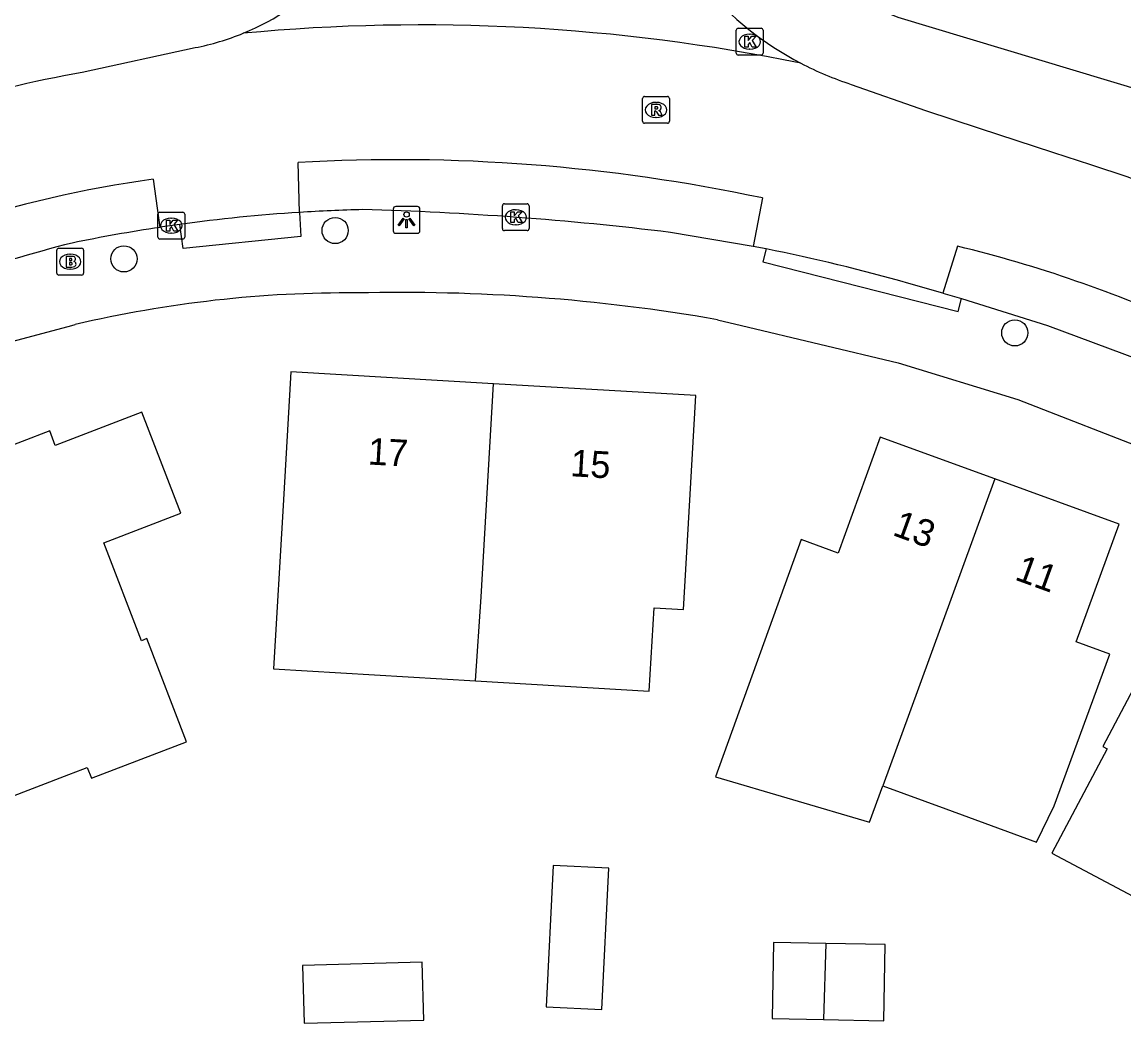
# Model space of a CAD drawing. Extents: x 161354 to 161876, y 382161 to 382804.
# Drawn here: x 161643.37 to 161684.52, y 382473.49 to 382511.32 of the extents above; entities that cross this region are included whole.
import ezdxf

# ---------------------------------------------------------------- set-up
doc = ezdxf.new("R2010")
doc.units = 0
for name, color, linetype in [('IMGEO_Boom', 7, 'Continuous'), ('IMGEO_Brandkraan', 7, 'Continuous'), ('IMGEO_Kolk', 7, 'Continuous'), ('IMGEO_Lichtpunt', 7, 'Continuous'), ('IMGEO_Pand', 7, 'Continuous'), ('IMGEO_Pand_nummerreeks', 7, 'Continuous'), ('IMGEO_Rijbaan_lokaal_gesloten', 7, 'Continuous'), ('IMGEO_Rijbaan_lokaal_open', 7, 'Continuous'), ('IMGEO_Rioolput', 7, 'Continuous'), ('IMGEO_Voetpad_open', 7, 'Continuous')]:
    doc.layers.add(name, color=color, linetype=linetype)

msp = doc.modelspace()

# ---------------------------------------------------------------- linework, layer by layer
at = {"layer": 'IMGEO_Boom'}
for centre in [(161655.065, 382503.541), (161647.18, 382502.485), (161680.442, 382499.723)]:
    msp.add_circle(centre, 0.489, dxfattribs=at)
at = {"layer": 'IMGEO_Brandkraan'}
for p, q in [((161644.672, 382501.953), (161644.672, 382502.805)), ((161644.747, 382502.879), (161645.599, 382502.879)), ((161645.16, 382502.659), (161645.185, 382502.659)), ((161645.673, 382502.805), (161645.673, 382501.953)), ((161645.183, 382502.099), (161645.158, 382502.099)), ((161645.599, 382501.879), (161644.747, 382501.879))]:
    msp.add_line(p, q, dxfattribs=at)
for points in [[(161644.672, 382501.953), (161644.672, 382502.805)], [(161644.747, 382502.879), (161645.599, 382502.879)], [(161645.02, 382502.579), (161645.02, 382502.179), (161645.233, 382502.179)], [(161645.251, 382502.579), (161645.02, 382502.579)], [(161645.199, 382502.498), (161645.145, 382502.498), (161645.145, 382502.422)], [(161645.673, 382502.805), (161645.673, 382501.953)], [(161645.145, 382502.422), (161645.198, 382502.422)], [(161645.207, 382502.346), (161645.145, 382502.346), (161645.145, 382502.265)], [(161645.145, 382502.265), (161645.207, 382502.265)], [(161645.599, 382501.879), (161644.747, 382501.879)]]:
    msp.add_lwpolyline(points, dxfattribs=at)
for centre, radius, start, end in [((161644.749, 382502.803), 0.0765, 91.552, 178.448), ((161644.749, 382502.803), 0.0765, 91.552, 178.448), ((161645.2, 382502.46), 0.0379, 267.8285, 90.9355), ((161645.255, 382502.434), 0.145, 59.4692, 91.5367), ((161645.28, 382502.481), 0.0922, 285.5137, 58.1501), ((161645.597, 382502.803), 0.0765, 1.552, 88.448), ((161645.597, 382502.803), 0.0765, 1.552, 88.448), ((161645.208, 382502.305), 0.0404, 269.8759, 90.5077), ((161645.239, 382502.43), 0.251, 268.6676, 293.5347), ((161645.285, 382502.289), 0.105, 301.3115, 78.989), ((161644.749, 382501.955), 0.0765, 181.552, 268.448), ((161644.749, 382501.955), 0.0765, 181.552, 268.448), ((161645.597, 382501.955), 0.0765, 271.552, 358.448), ((161645.597, 382501.955), 0.0765, 271.552, 358.448)]:
    msp.add_arc(centre, radius, start, end, dxfattribs=at)
for centre, major_axis, ratio, start_param, end_param in [((161645.159, 382502.379), (-0.387, 0.002), 0.722429, 4.712389, 7.853982), ((161645.184, 382502.379), (-0.39, 0.002), 0.717154, 1.570796, 4.712389)]:
    msp.add_ellipse(centre, major_axis=major_axis, ratio=ratio, start_param=start_param, end_param=end_param, dxfattribs=at)
at = {"layer": 'IMGEO_Kolk'}
for p, q in [((161670.044, 382510.163), (161670.044, 382511.015)), ((161670.119, 382511.089), (161670.971, 382511.089)), ((161670.532, 382510.869), (161670.557, 382510.869)), ((161671.045, 382511.015), (161671.045, 382510.163)), ((161670.555, 382510.309), (161670.53, 382510.309)), ((161670.971, 382510.089), (161670.119, 382510.089)), ((161661.383, 382504.538), (161662.235, 382504.538)), ((161648.447, 382503.298), (161648.447, 382504.15)), ((161648.522, 382504.224), (161649.374, 382504.224)), ((161649.448, 382504.15), (161649.448, 382503.298)), ((161661.308, 382503.612), (161661.308, 382504.464)), ((161661.796, 382504.318), (161661.821, 382504.318)), ((161662.309, 382504.464), (161662.309, 382503.612)), ((161648.935, 382504.004), (161648.96, 382504.004)), ((161661.819, 382503.758), (161661.794, 382503.758)), ((161648.958, 382503.444), (161648.933, 382503.444)), ((161662.235, 382503.538), (161661.383, 382503.538)), ((161649.374, 382503.224), (161648.522, 382503.224))]:
    msp.add_line(p, q, dxfattribs=at)
for points in [[(161670.044, 382510.163), (161670.044, 382511.015)], [(161670.119, 382511.089), (161670.971, 382511.089)], [(161670.365, 382510.789), (161670.488, 382510.789), (161670.488, 382510.638), (161670.618, 382510.789), (161670.782, 382510.789), (161670.636, 382510.638), (161670.789, 382510.389), (161670.637, 382510.389), (161670.552, 382510.553), (161670.488, 382510.486), (161670.488, 382510.389), (161670.365, 382510.389), (161670.365, 382510.789)], [(161671.045, 382511.015), (161671.045, 382510.163)], [(161670.971, 382510.089), (161670.119, 382510.089)], [(161661.383, 382504.538), (161662.235, 382504.538)], [(161648.447, 382503.298), (161648.447, 382504.15)], [(161648.522, 382504.224), (161649.374, 382504.224)], [(161649.448, 382504.15), (161649.448, 382503.298)], [(161661.308, 382503.612), (161661.308, 382504.464)], [(161661.629, 382504.238), (161661.752, 382504.238), (161661.752, 382504.087), (161661.882, 382504.238), (161662.046, 382504.238), (161661.9, 382504.087), (161662.053, 382503.838), (161661.901, 382503.838), (161661.816, 382504.002), (161661.752, 382503.935), (161661.752, 382503.838), (161661.629, 382503.838), (161661.629, 382504.238)], [(161662.309, 382504.464), (161662.309, 382503.612)], [(161648.768, 382503.924), (161648.891, 382503.924), (161648.891, 382503.773), (161649.021, 382503.924), (161649.185, 382503.924), (161649.039, 382503.773), (161649.192, 382503.524), (161649.04, 382503.524), (161648.955, 382503.688), (161648.891, 382503.621), (161648.891, 382503.524), (161648.768, 382503.524), (161648.768, 382503.924)], [(161662.235, 382503.538), (161661.383, 382503.538)], [(161649.374, 382503.224), (161648.522, 382503.224)]]:
    msp.add_lwpolyline(points, dxfattribs=at)
for centre, start, end in [((161670.121, 382511.013), 91.552, 178.448), ((161670.121, 382511.013), 91.552, 178.448), ((161670.969, 382511.013), 1.552, 88.448), ((161670.969, 382511.013), 1.552, 88.448), ((161670.121, 382510.165), 181.552, 268.448), ((161670.121, 382510.165), 181.552, 268.448), ((161670.969, 382510.165), 271.552, 358.448), ((161670.969, 382510.165), 271.552, 358.448), ((161661.385, 382504.462), 91.552, 178.448), ((161661.385, 382504.462), 91.552, 178.448), ((161662.233, 382504.462), 1.552, 88.448), ((161662.233, 382504.462), 1.552, 88.448), ((161648.524, 382504.148), 91.552, 178.448), ((161648.524, 382504.148), 91.552, 178.448), ((161649.372, 382504.148), 1.552, 88.448), ((161649.372, 382504.148), 1.552, 88.448), ((161661.385, 382503.614), 181.552, 268.448), ((161661.385, 382503.614), 181.552, 268.448), ((161662.233, 382503.614), 271.552, 358.448), ((161662.233, 382503.614), 271.552, 358.448), ((161648.524, 382503.3), 181.552, 268.448), ((161648.524, 382503.3), 181.552, 268.448), ((161649.372, 382503.3), 271.552, 358.448), ((161649.372, 382503.3), 271.552, 358.448)]:
    msp.add_arc(centre, 0.0765, start, end, dxfattribs=at)
for centre, major_axis, ratio, start_param, end_param in [((161670.531, 382510.589), (-0.387, 0.002), 0.722429, 4.712389, 7.853982), ((161670.556, 382510.589), (-0.39, 0.002), 0.717154, 1.570796, 4.712389), ((161661.795, 382504.038), (-0.387, 0.002), 0.722429, 4.712389, 7.853982), ((161661.82, 382504.038), (-0.39, 0.002), 0.717154, 1.570796, 4.712389), ((161648.934, 382503.724), (-0.387, 0.002), 0.722429, 4.712389, 7.853982), ((161648.959, 382503.724), (-0.39, 0.002), 0.717154, 1.570796, 4.712389)]:
    msp.add_ellipse(centre, major_axis=major_axis, ratio=ratio, start_param=start_param, end_param=end_param, dxfattribs=at)
at = {"layer": 'IMGEO_Lichtpunt'}
for p, q in [((161657.234, 382504.343), (161657.234, 382503.536)), ((161657.234, 382504.343), (161657.234, 382503.536)), ((161658.136, 382504.438), (161657.328, 382504.438)), ((161658.136, 382504.438), (161657.328, 382504.438)), ((161658.23, 382503.536), (161658.23, 382504.343)), ((161658.23, 382503.536), (161658.23, 382504.343)), ((161657.328, 382503.442), (161658.136, 382503.442)), ((161657.328, 382503.442), (161658.136, 382503.442))]:
    msp.add_line(p, q, dxfattribs=at)
for points in [[(161657.608, 382504.007), (161657.647, 382503.979), (161657.459, 382503.717), (161657.421, 382503.744), (161657.608, 382504.007)], [(161657.71, 382503.959), (161657.757, 382503.959), (161657.757, 382503.637), (161657.71, 382503.637), (161657.71, 382503.959)], [(161657.82, 382503.979), (161657.858, 382504.006), (161658.045, 382503.744), (161658.006, 382503.716), (161657.82, 382503.979)]]:
    msp.add_lwpolyline(points, dxfattribs=at)
msp.add_circle((161657.733, 382504.141), 0.0994, dxfattribs=at)
for centre, start, end in [((161657.328, 382504.343), 90, 180), ((161657.328, 382504.343), 90, 180), ((161658.136, 382504.343), 0, 90), ((161658.136, 382504.343), 0, 90), ((161657.328, 382503.536), 180, 270), ((161657.328, 382503.536), 180, 270), ((161658.136, 382503.536), 270, 0), ((161658.136, 382503.536), 270, 360)]:
    msp.add_arc(centre, 0.0946, start, end, dxfattribs=at)
at = {"layer": 'IMGEO_Pand'}
for points in [[(161660.977, 382497.827), (161653.413, 382498.267), (161653.123, 382493.276), (161652.769, 382487.186), (161660.303, 382486.738)], [(161660.303, 382486.738), (161660.518, 382489.873), (161660.977, 382497.827)], [(161660.303, 382486.738), (161666.795, 382486.352), (161666.976, 382489.466), (161668.074, 382489.402), (161668.248, 382492.397), (161668.538, 382497.388), (161660.977, 382497.827)], [(161645.122, 382483.242), (161645.64, 382483.44), (161645.812, 382483.507), (161645.967, 382483.104), (161649.518, 382484.468), (161648.04, 382488.313), (161647.836, 382488.235), (161646.431, 382491.89), (161649.301, 382492.993), (161647.851, 382496.767), (161644.616, 382495.524), (161644.408, 382496.064), (161637.168, 382493.282), (161637.371, 382492.753), (161634.217, 382491.541), (161635.711, 382487.653), (161638.861, 382488.811), (161640.417, 382484.76), (161641.53, 382481.862), (161645.122, 382483.242)], [(161679.692, 382494.275), (161675.419, 382495.83), (161673.845, 382491.507), (161672.468, 382492.008), (161669.27, 382483.151), (161675.014, 382481.469), (161675.514, 382482.827)], [(161675.514, 382482.827), (161677.868, 382481.963), (161681.248, 382480.722), (161681.915, 382482.074), (161683.994, 382487.733), (161682.738, 382488.19), (161684.337, 382492.585), (161679.692, 382494.275)], [(161679.692, 382494.275), (161676.515, 382485.55), (161675.514, 382482.827)], [(161690.573, 382480.619), (161694.333, 382487.718), (161691.193, 382489.381), (161690.745, 382490.839), (161688.84, 382491.848), (161687.832, 382491.216), (161687.493, 382491.396), (161683.726, 382484.284), (161683.885, 382484.2), (161681.819, 382480.303), (161686.068, 382478.054), (161690.573, 382480.619)], [(161665.02, 382474.473), (161665.278, 382479.751), (161663.207, 382479.852), (161662.949, 382474.574), (161665.02, 382474.473)], [(161673.39, 382476.938), (161671.434, 382476.974), (161671.382, 382474.135), (161673.297, 382474.099)], [(161673.39, 382476.938), (161673.297, 382474.099)], [(161673.297, 382474.099), (161675.547, 382474.058), (161675.6, 382476.897), (161673.39, 382476.938)], [(161653.85, 382476.122), (161653.905, 382473.965), (161658.375, 382474.081), (161658.319, 382476.237), (161653.85, 382476.122)]]:
    msp.add_lwpolyline(points, dxfattribs=at)
at = {"layer": 'IMGEO_Rijbaan_lokaal_gesloten'}
for centre, radius, start, end in [((161647.988, 382519.82), 9.633, 292.2506, 339.1549), ((161678.097, 382520.597), 12.195, 220.6649, 242.4236), ((161658.279, 382440.187), 71.028, 78.49035, 95.36619)]:
    msp.add_arc(centre, radius, start, end, dxfattribs=at)
at = {"layer": 'IMGEO_Rijbaan_lokaal_open'}
for points in [[(161649.833, 382510.365), (161645.624, 382509.44)], [(161674.333, 382508.996), (161677.108, 382508.026), (161679.107, 382507.366), (161681.884, 382506.459), (161683.272, 382506.002), (161684.661, 382505.544), (161686.809, 382504.682), (161688.569, 382503.883)], [(161653.732, 382504.218), (161653.68, 382506.082)], [(161648.273, 382505.457), (161648.523, 382503.661)], [(161671.016, 382504.756), (161670.674, 382502.94)], [(161671.155, 382502.857), (161670.674, 382502.94)], [(161678.3, 382502.959), (161677.758, 382501.202)], [(161677.758, 382501.202), (161676.485, 382501.569)]]:
    msp.add_lwpolyline(points, dxfattribs=at)
for centre, radius, start, end in [((161648.015, 382519.733), 9.542, 280.9851, 292.3026), ((161678.078, 382520.54), 12.136, 242.3785, 252.0277), ((161652.586, 382469.194), 40.843, 99.815, 107.7247), ((161657.38, 382440.467), 65.719, 78.02467, 93.22745), ((161653.892, 382464.23), 41.608, 97.7606, 119.1819), ((161657.562, 382443.8), 60.54, 93.62749, 97.87751), ((161655.648, 382456.881), 47.32, 97.7519, 98.6596), ((161666.702, 382455.35), 49.001, 65.516, 76.3088), ((161657.932, 382436.465), 67.696, 74.09372, 78.73599)]:
    msp.add_arc(centre, radius, start, end, dxfattribs=at)
at = {"layer": 'IMGEO_Rioolput'}
for p, q in [((161666.545, 382507.618), (161666.545, 382508.47)), ((161666.62, 382508.544), (161667.472, 382508.544)), ((161667.033, 382508.324), (161667.058, 382508.324)), ((161667.546, 382508.47), (161667.546, 382507.618)), ((161667.472, 382507.544), (161666.62, 382507.544)), ((161667.056, 382507.764), (161667.031, 382507.764))]:
    msp.add_line(p, q, dxfattribs=at)
for points in [[(161666.545, 382507.618), (161666.545, 382508.47)], [(161666.62, 382508.544), (161667.472, 382508.544)], [(161667.134, 382508.242), (161666.882, 382508.244), (161666.882, 382507.844)], [(161667.546, 382508.47), (161667.546, 382507.618)], [(161666.882, 382507.844), (161667.006, 382507.844), (161667.006, 382508.006), (161667.017, 382508.006)], [(161667.06, 382508.163), (161667.006, 382508.163), (161667.006, 382508.082)], [(161667.006, 382508.082), (161667.058, 382508.082)], [(161667.064, 382507.977), (161667.135, 382507.844), (161667.275, 382507.844), (161667.21, 382507.97)], [(161667.472, 382507.544), (161666.62, 382507.544)]]:
    msp.add_lwpolyline(points, dxfattribs=at)
for centre, radius, start, end in [((161666.622, 382508.468), 0.0765, 91.552, 178.448), ((161666.622, 382508.468), 0.0765, 91.552, 178.448), ((161667.133, 382508.132), 0.109, 350.3612, 89.416), ((161667.47, 382508.468), 0.0765, 1.552, 88.448), ((161667.47, 382508.468), 0.0765, 1.552, 88.448), ((161667.016, 382507.953), 0.0533, 26.0293, 88.6989), ((161667.042, 382508.271), 0.19, 274.7715, 282.9687), ((161667.066, 382508.067), 0.0964, 77.0061, 93.1865), ((161667.08, 382508.124), 0.0378, 276.6634, 79.6772), ((161667.131, 382508.132), 0.112, 277.5842, 350.9817), ((161667.115, 382507.917), 0.108, 29.5134, 73.7905), ((161666.622, 382507.62), 0.0765, 181.552, 268.448), ((161666.622, 382507.62), 0.0765, 181.552, 268.448), ((161667.47, 382507.62), 0.0765, 271.552, 358.448), ((161667.47, 382507.62), 0.0765, 271.552, 358.448)]:
    msp.add_arc(centre, radius, start, end, dxfattribs=at)
for centre, major_axis, ratio, start_param, end_param in [((161667.032, 382508.044), (-0.387, 0.002), 0.722429, 4.712389, 7.853982), ((161667.057, 382508.044), (-0.39, 0.002), 0.717154, 1.570796, 4.712389)]:
    msp.add_ellipse(centre, major_axis=major_axis, ratio=ratio, start_param=start_param, end_param=end_param, dxfattribs=at)
at = {"layer": 'IMGEO_Voetpad_open'}
for points in [[(161671.192, 382513.811), (161672.294, 382513.039), (161676.079, 382511.506), (161686.582, 382508.346), (161693.296, 382505.713), (161699.526, 382502.596), (161701.857, 382501.312), (161704.194, 382500.041), (161707.056, 382498.523), (161714.17, 382494.92), (161716.027, 382493.968), (161718.402, 382492.765), (161721.484, 382491.299)], [(161653.732, 382504.218), (161653.79, 382503.325), (161649.386, 382502.868), (161649.265, 382503.768)], [(161670.674, 382502.94), (161667.582, 382503.472)], [(161671.155, 382502.857), (161671.031, 382502.373), (161678.326, 382500.519), (161678.45, 382501.003)], [(161677.758, 382501.202), (161678.45, 382501.003)], [(161678.45, 382501.003), (161681.661, 382500), (161686.249, 382498.297)], [(161599.51, 382473.488), (161629.702, 382492.691), (161638.917, 382498.07), (161640.973, 382498.872), (161645.238, 382500), (161645.363, 382500.033)], [(161669.342, 382500.214), (161670.239, 382500), (161676.089, 382498.604), (161680.55, 382497.241), (161685.666, 382495.251), (161690.713, 382493.092), (161712.747, 382481.646), (161718.908, 382479.002)]]:
    msp.add_lwpolyline(points, dxfattribs=at)
for centre, radius, start, end in [((161657.699, 382441.042), 63.3, 91.45562, 93.59305), ((161652.932, 382383.512), 120.851, 83.03706, 88.50191), ((161657.5, 382443.998), 60.334, 98.55709, 101.72367), ((161657.629, 382453.855), 50.754, 104.1279, 114.6068), ((161655.544, 382456.789), 44.426, 89.5615, 103.2479), ((161657.511, 382432.058), 69.175, 80.15274, 91.34812)]:
    msp.add_arc(centre, radius, start, end, dxfattribs=at)

# ---------------------------------------------------------------- texts
at = {"layer": 'IMGEO_Pand_nummerreeks'}
for s, rotation, p in [('17', 356.674, (161656.27, 382494.815)), ('15', 356.674, (161663.832, 382494.376)), ('13', 340.005, (161675.836, 382492.188)), ('11', 340.005, (161680.402, 382490.526))]:
    msp.add_text(s, height=1, rotation=rotation, dxfattribs=at).set_placement(p)

doc.saveas('drawing.dxf')
